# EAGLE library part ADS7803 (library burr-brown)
Autocalibrating, 4-Channel, 12-Bit ADC
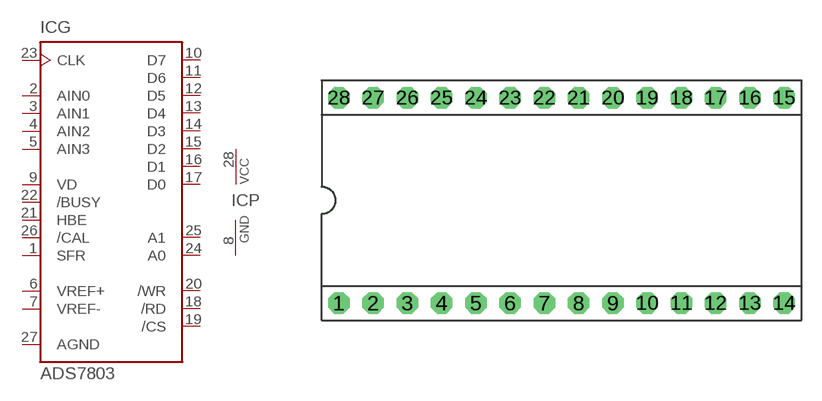
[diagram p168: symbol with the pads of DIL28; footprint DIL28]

Designator prefix IC; gates P=PWRN G=ADS7803

## ADS7803P (OC_FARNELL: unknown; OC_NEWARK: unknown)  [DIL28]
1  G:SFR  in
2  G:AIN0  in
3  G:AIN1  in
4  G:AIN2  in
5  G:AIN3  in
6  G:VREF+
7  G:VREF-
8  P:GND  pwr
9  G:VD
10  G:D7  hiz
11  G:D6  hiz
12  G:D5  hiz
13  G:D4  hiz
14  G:D3  hiz
15  G:D2  hiz
16  G:D1  hiz
17  G:D0  hiz
18  G:/RD  in
19  G:/CS  in
20  G:/WR  in
21  G:HBE  in
22  G:/BUSY  in
23  G:CLK  in
24  G:A0  in
25  G:A1  in
26  G:/CAL  in
27  G:AGND  pwr
28  P:VCC  pwr

## Footprint DIL28 (pad centres in mm)
Dual In Line
drill 0.813 pad 1.6 octagon: 1 -16.51,-7.62; 2 -13.97,-7.62; 3 -11.43,-7.62; 4 -8.89,-7.62; 5 -6.35,-7.62; 6 -3.81,-7.62; 7 -1.27,-7.62; 8 1.27,-7.62; 9 3.81,-7.62; 10 6.35,-7.62; 11 8.89,-7.62; 12 11.43,-7.62; 13 13.97,-7.62; 14 16.51,-7.62; 15 16.51,7.62; 16 13.97,7.62; 17 11.43,7.62; 18 8.89,7.62; 19 6.35,7.62; 20 3.81,7.62; 21 1.27,7.62; 22 -1.27,7.62; 23 -3.81,7.62; 24 -6.35,7.62; 25 -8.89,7.62; 26 -11.43,7.62; 27 -13.97,7.62; 28 -16.51,7.62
